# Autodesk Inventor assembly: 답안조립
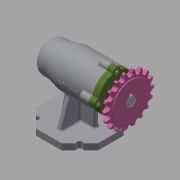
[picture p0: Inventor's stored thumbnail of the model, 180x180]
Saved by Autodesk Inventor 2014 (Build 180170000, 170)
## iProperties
Created: 2021-01
Part Number: 답안조립
Document SubType Name: Assembly
Designer: kh
Author: kh
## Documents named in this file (12)
- C:\Users\kh\Desktop\가마우지\710106V1014\답안조립.iam
- C:\Users\kh\Desktop\가마우지\710106V1014\본체.ipt
- C:\Users\kh\Desktop\가마우지\710106V1014\멈춤나사 M3.ipt
- C:\Users\kh\Desktop\가마우지\710106V1014\베어링 6004.ipt
- C:\Users\kh\Desktop\가마우지\710106V1014\베어링 51202.ipt
- C:\Users\kh\Desktop\가마우지\710106V1014\볼트 M4.ipt
- C:\Users\kh\Desktop\가마우지\710106V1014\스프로킷.ipt
- C:\Users\kh\Desktop\가마우지\710106V1014\어댑터슬리브.ipt
- C:\Users\kh\Desktop\가마우지\710106V1014\오일 실.ipt
- C:\Users\kh\Desktop\가마우지\710106V1014\축.ipt
- C:\Users\kh\Desktop\가마우지\710106V1014\커버.ipt
- C:\Users\kh\Desktop\가마우지\710106V1014\키 5 x 5 x 14.ipt
